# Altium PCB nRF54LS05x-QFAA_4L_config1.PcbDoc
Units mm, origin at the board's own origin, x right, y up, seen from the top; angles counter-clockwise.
Board outline 15 x 12 mm, 4 copper layers (Top Layer, Mid-Layer 1, Mid-Layer 2, Bottom Layer), stack 1.64 mm thick; 21 components, 51 nets, 91 pads, 73 vias.
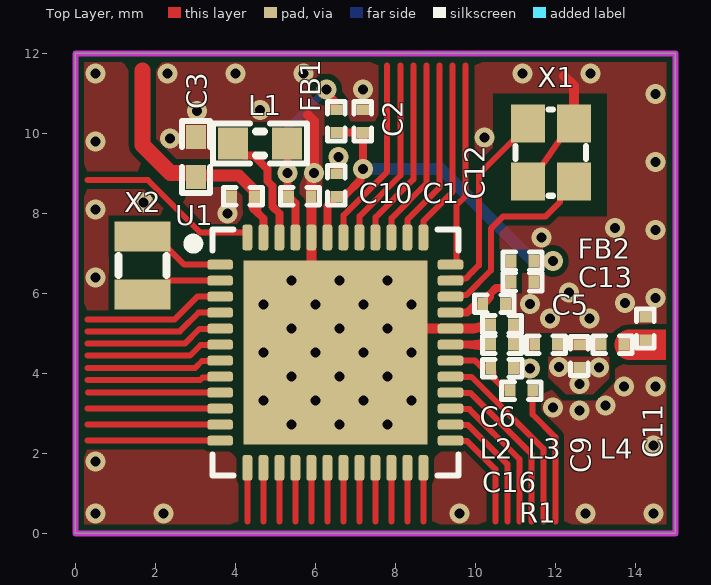
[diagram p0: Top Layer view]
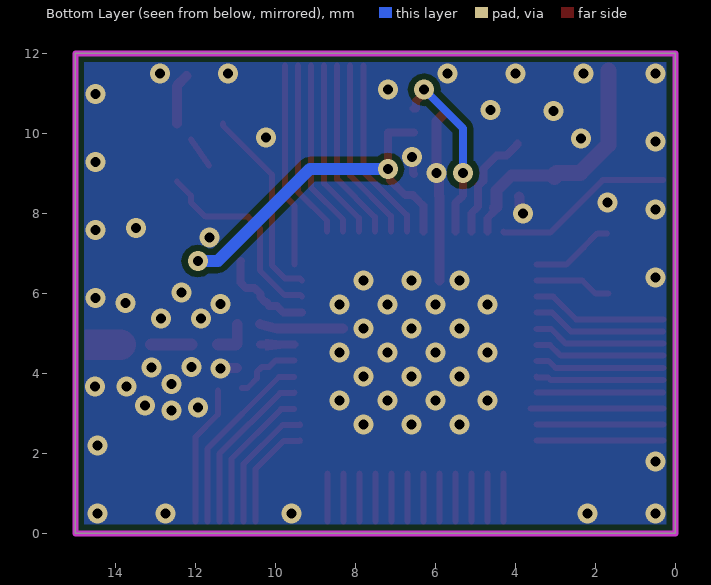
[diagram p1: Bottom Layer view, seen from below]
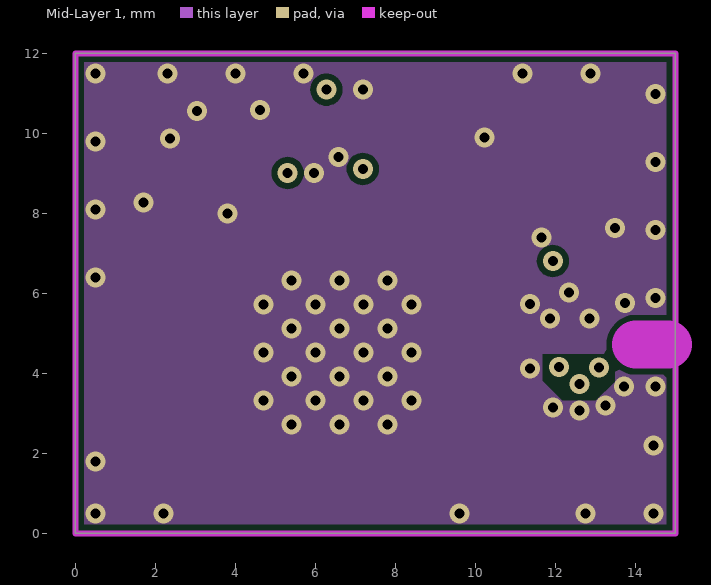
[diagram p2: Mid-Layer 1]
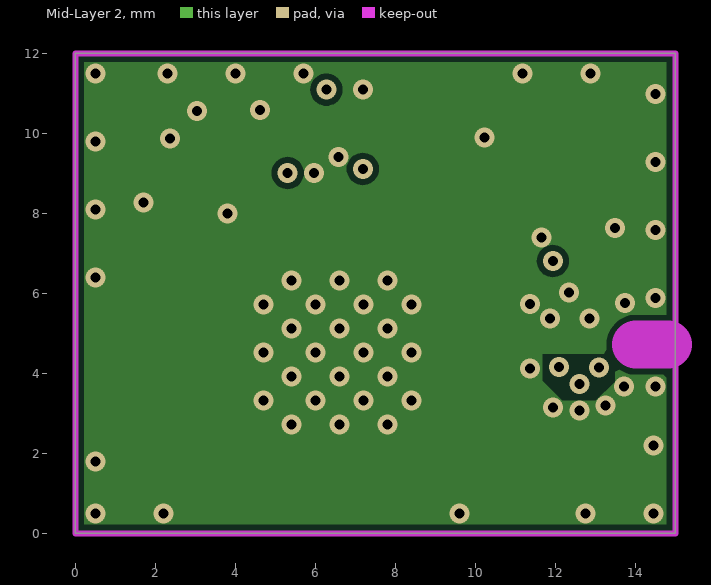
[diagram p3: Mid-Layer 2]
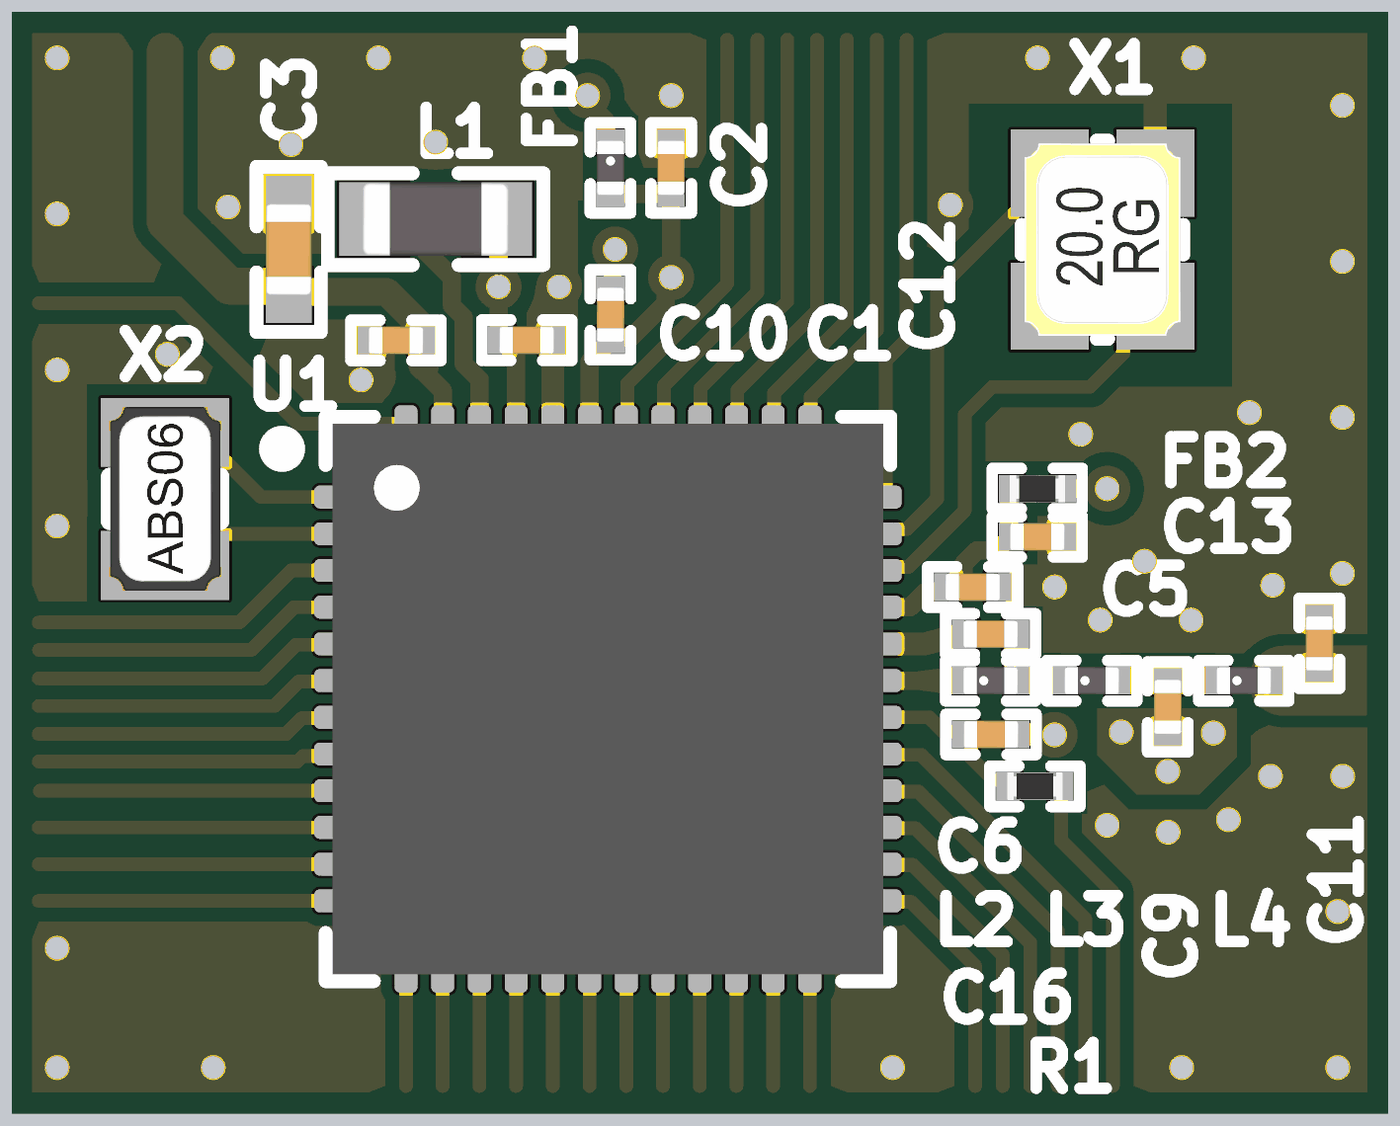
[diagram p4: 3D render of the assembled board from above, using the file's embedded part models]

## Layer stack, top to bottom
Top Solder: solder mask 0.0102, Solder Resist, Dk 3.5
Top Layer: signal copper 0.035
Dielectric 1: prepreg 0.1, 1080, Dk 4.3
Mid-Layer 1: signal copper 0.035
Dielectric 2: core 1.3, Core-042, Dk 4.6
Mid-Layer 2: signal copper 0.035
Dielectric 3: prepreg 0.1, 1080, Dk 4.3
Bottom Layer: signal copper 0.035
Bottom Solder: solder mask 0.0102, Solder Resist, Dk 3.5

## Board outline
0,0 0,12 15,12 15,0

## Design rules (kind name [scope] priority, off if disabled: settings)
Clearance Polygon_ANT [(InNamedPolygon('Top_Layer-GND')) or IsFill or IsRegion vs InNet('RF')] p1: gap=0.127 ignorepadtopadclearanceinfootprint=FALSE
Clearance Polygon [(InNamedPolygon('Top_Layer-GND'))  or (InNamedPolygon('Bottom_Layer-GND'))] p2: gap=0.15 ignorepadtopadclearanceinfootprint=FALSE
Clearance [All] p3: gap=0.15 ignorepadtopadclearanceinfootprint=FALSE
ComponentClearance [All] p1 off: gap=0.254 collisioncheckmode=3 verticalgap=0.254 showdistances=FALSE
FabricationTestPointUsage TestPointUsage [All] p1: valid=0 allowmultiple=FALSE
FabricationTestpoint Testpoint [All] p1: side=3 testpointundercomponent=TRUE minsize=1.016 maxsize=2.54 preferedsize=1.524 minholesize=0 maxholesize=1.016 preferedholesize=0.813 testpointgrid=0.025 allowsidetop=TRUE allowsidebottom=TRUE usegrid=TRUE gridtolerance=0
Height [All] p1 off: minheight=0 maxheight=25.4 prefheight=12.7
HoleSize [All] p1: absolutevalues=TRUE maxlimit=4.064 minlimit=0.2 maxpercent=80.000 minpercent=20.000
HoleToHoleClearance [All] p1: gap=0.36 allowstackedmicrovias=TRUE
MinimumAnnularRing [All] p1 off: minimumring=0.152
MinimumSolderMaskSliver [All] p1: minsoldermaskwidth=0.09
PlaneClearance [All] p1: clearance=0.2
PolygonConnect PolygonConnect_SMD_PADs [InComponent('C1','C2','C3','C4','C5','C7','C8','C9','C10','C11','C12','C13','C16') vs InNet('GND')] p1: connectstyle=Direct reliefconductorwidth=0.254 reliefentries=4 polygonreliefangle="90 Angle" airgapwidth=0.254
PolygonConnect PolygonConnect_GND_VIAs [isVia and innet(gnd)] p2: connectstyle=Direct reliefconductorwidth=0.254 reliefentries=4 polygonreliefangle="90 Angle" airgapwidth=0.254
PolygonConnect [All] p3: thpad.connectstyle=Relief thpad.reliefconductorwidth=0.25 thpad.reliefentries=4 thpad.polygonreliefangle="90 Angle" thpad.airgapwidth=0.2 smdpad.connectstyle=Relief smdpad.reliefconductorwidth=0.25 smdpad.reliefentries=4 smdpad.polygonreliefangle="90 Angle" smdpad.airgapwidth=0.2 via.connectstyle=Direct via.reliefconductorwidth=0.254 via.reliefentries=4 via.polygonreliefangle="90 Angle" via.airgapwidth=0.254
RoutingVias [All] p1: holewidth=0.406 width=0.813 viastyle="Through Hole" minholewidth=0.2 minwidth=0.4 maxholewidth=0.711 maxwidth=1.27
SilkToSolderMaskClearance SilkscreenOverComponentPads [IsPad] p1: minsilkscreentomaskgap=0.254 clearancetoexposedcopper=TRUE
SolderMaskExpansion SolderMaskExpansion_via [IsVia] p1: expansion=0.102 istentingtop=TRUE
SolderMaskExpansion [All] p2: expansion=0.03 istentingtop=FALSE
Width [All] p1: maxlimit=2.54 minlimit=0.15 preferedwidth=0.15
21 further rules are at their usual default settings.

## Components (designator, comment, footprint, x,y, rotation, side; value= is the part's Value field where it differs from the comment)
C1 "2.2µF" CAPC0603X03L_C 5.615,8.425 r180 top
C2 "2.2µF" CAPC0603X03L_C 7.188,10.303 r270 top
C3 "10µF" CAPC1005X04L 3.023,9.414 r270 top
C5 "10nF" CAPC0603X03L_C 10.473,5.735 r180 top
C6 "1.5pF" CAPC0603X03L_C 10.668,5.223 r0 top
C9 "2.0pF" CAPC0603X03L_C 12.598,4.43 r90 top
C10 "100nF" CAPC0603X03L_C 4.191,8.423 r0 top
C11 "0.3pF" CAPC0603X03L_C 14.249,5.121 r270 top
C12 "2.2µF" CAPC0603X03L_C 6.528,8.703 r90 top
C13 "2.2µF" CAPC0603X03L_C 11.177,6.283 r0 top
C16 "3.9pF" CAPC0603X03L_C 10.673,4.13 r0 top
FB1 "120R/0.2A" INDC0603X03L_C 6.528,10.303 r270 top
FB2 "0R" RESC0603X03L_C 11.177,6.807 r0 top
L1 "4.7µH" INDC1608X06L 4.623,9.744 r0 top
L2 "2.7nH" INDC0603X03L_C 10.668,4.715 r0 top
L3 "3.5nH" INDC0603X03L_C 11.77,4.715 r0 top
L4 "3.5nH" INDC0603X03L_C 13.426,4.715 r0 top
R1 "0R" RESC0603X03L_C 11.151,3.564 r0 top
U1 "nRF54LS05B-QFAA" QFN49P40_600x600x90L40x20T460N 6.5,4.516 r0 top locked
X1 "32MHz" BT-XTAL_2016 11.887,9.52 r90 top
X2 "32.768kHz" XTAL_2012 1.676,6.696 r90 top

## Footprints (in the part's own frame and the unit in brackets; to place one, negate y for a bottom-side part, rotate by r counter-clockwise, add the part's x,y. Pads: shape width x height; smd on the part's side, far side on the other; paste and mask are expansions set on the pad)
BT-XTAL_2016 [mm] "Crystal 2.0 x 1.6 mm"
  rect 0.95x0.85 smd: 1(-0.725,-0.575) 2(0.725,-0.575) 3(0.725,0.575) 4(-0.725,0.575)
  silkscreen extent -1.08,-0.88 1.08,0.88, body extent -1.05,-0.85 1.05,0.85, height 0.56
CAPC0603X03L_C [mm] "Chip Capacitor, 2-Leads, Body 0.6x0.3mm, IPC High Density"
  rect 0.27x0.3 smd mask+0.05: 1(-0.285,0) 2(0.285,0)
  silkscreen extent -0.49,-0.22 0.49,0.22, body extent -0.3,-0.15 0.3,0.15, height 0.3
CAPC1005X04L [mm] "Chip Capacitor, 2-Leads, Body 1.0x0.5mm, IPC High Density"
  rect 0.6x0.5 smd: 1(-0.5,0) 2(0.5,0)
  silkscreen extent -0.9,-0.35 0.9,0.35, body extent -0.5,-0.25 0.5,0.25, height 0.5
INDC0603X03L_C [mm] "Chip Inductor, 2-Leads, Body 0.6x0.3mm, IPC High Density"
  rect 0.27x0.3 smd: 1(-0.285,0) 2(0.285,0)
  silkscreen extent -0.49,-0.22 0.49,0.22, body extent -0.3,-0.15 0.3,0.15, height 0.3
INDC1608X06L [mm] "Chip Inductor, 2-Leads, Body 1.6x0.8mm, IPC High Density"
  rect 0.75x0.8 smd: 1(-0.675,0) 2(0.675,0)
  silkscreen extent -1.17,-0.5 1.17,0.5, body extent -0.8,-0.4 0.8,0.4, height 0.8
QFN49P40_600x600x90L40x20T460N [mm] "QFN, 48-Leads, Body 6.00x6.00mm, Pitch 0.40mm, Thermal Pad 4.60x4.60mm, IPC Nominal Density"
  rrect50% 0.64x0.25 smd mask+0.03: 1(-2.88,2.2) 2(-2.88,1.8) 3(-2.88,1.4) 4(-2.88,1) 5(-2.88,0.6) 6(-2.88,0.2) 7(-2.88,-0.2) 8(-2.88,-0.6) 9(-2.88,-1) 10(-2.88,-1.4) 11(-2.88,-1.8) 12(-2.88,-2.2) 25(2.88,-2.2) 26(2.88,-1.8) 27(2.88,-1.4) 28(2.88,-1) 29(2.88,-0.6) 30(2.88,-0.2) 31(2.88,0.2) 32(2.88,0.6) 33(2.88,1) 34(2.88,1.4) 35(2.88,1.8) 36(2.88,2.2)
  rrect50% 0.25x0.64 smd mask+0.03: 13(-2.2,-2.88) 14(-1.8,-2.88) 15(-1.4,-2.88) 16(-1,-2.88) 17(-0.6,-2.88) 18(-0.2,-2.88) 19(0.2,-2.88) 20(0.6,-2.88) 21(1,-2.88) 22(1.4,-2.88) 23(1.8,-2.88) 24(2.2,-2.88) 37(2.2,2.88) 38(1.8,2.88) 39(1.4,2.88) 40(1,2.88) 41(0.6,2.88) 42(0.2,2.88) 43(-0.2,2.88) 44(-0.6,2.88) 45(-1,2.88) 46(-1.4,2.88) 47(-1.8,2.88) 48(-2.2,2.88)
  rect 4.6x4.6 smd mask+0.05: 49(0,0)
  silkscreen extent -3.67,-3.08 3.08,3.08, body extent -3,-3 3,3, height 0.9
RESC0603X03L_C [mm] "Chip Resistor, 2-Leads, Body 0.6x0.3mm, IPC High Density"
  rect 0.27x0.3 smd: 1(-0.285,0) 2(0.285,0)
  silkscreen extent -0.49,-0.22 0.49,0.22, body extent -0.3,-0.15 0.3,0.15, height 0.23
XTAL_2012 [mm] "XTAL SMD 2.0 x 1.2 mm"
  rect 0.75x1.4 smd: 1(-0.725,0) 2(0.725,0)
  silkscreen extent -0.24,-0.6 0.24,0.6, body extent -1,-0.61 1,0.61, height 0.6

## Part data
C1 C2 C12 C13: library part C0201-2µ2-2.5V-X6T-GRM033D80E225ME47D, "Capacitor, Ceramic, 2.2µF 2.5V X6T 0201,±20%", Manufacturer=Murata, Manufacturer Part Number=GRM033D80E225ME47D, Part number IPS=N.A., Part number NEMS=100200527, Supplier Part Number 1=81-GRM033D80E225ME7D
C3: library part C0402-10µF-6.3V-X6S, "Capacitor, X6S, ±20%, 6.3V", Manufacturer=N.A., Part number NEMS=100200478
C5: library part C0201-10n-6.3V-X7R, "Capacitor, X7R, 6.3V", Manufacturer=Murata, Manufacturer Part Number=GRM033R70J103KA01D, Part number IPS=N.A., Part number NEMS=100200407, Supplier Part Number 1=490-1262-1-ND
C6: library part C0201-1.5p-25V-NP0-GJM0335C1E1R5WB01, "Capacitor, NP0, ±0.05pF, 25V, High Q", Manufacturer=Murata, Manufacturer Part Number=GJM0335C1E1R5WB01, Part number IPS=N.A., Part number NEMS=100200477, Supplier Part Number 1=490-11176-2-ND
C9: library part C0201-2.0p-HQ-Murata, "Capacitor, NP0, ±0.05pF, 25V", Manufacturer=Murata, Manufacturer Part Number=GJM0335C1E2R0WB01, Part number IPS=00000001775, Part number NEMS=100200419, Part number Norautron=N.A.
C10: library part C0201-100n-10V-X7R, "Capacitor, X7R, ±10%, 10V", Manufacturer=N.A., Part number NEMS=100200469
C11: library part C0201-0.3p-50V-GRM0335C1HR30BA01, "Capacitor, C0G, ±0.1pF, 50V", Manufacturer=Murata, Manufacturer Part Number=GRM0335C1HR30BA01, Part number IPS=N.A., Part number NEMS=100200650, Supplier Part Number 1=490-6135-2-ND
C16: library part C0201-3.9p, "Chip Cap 0201", Manufacturer=N.A., Part number NEMS=100200024,100200424
FB1: library part FB0201-120R@100M-200mA-BLM03AG121SN1D, "Ferrite Bead, 120 Ohm @ 100MHz, 200mA, 500 mOhm Max", Manufacturer=Murata, Manufacturer Part Number=BLM03AG121SN1D, Part number IPS=N.A., Part number NEMS=100300419, Supplier Part Number 1=490-5622-1-ND
FB2 R1: library part R0201-0R-5%-0.05W-RC0201JR-070RL, "0 Ohms Jumper 0.05W, 1/20W Chip Resistor 0201 (0603 Metric) Moisture Resistant Thick Film", Manufacturer=Yageo, Manufacturer Part Number=RC0201JR-070RL, Part number IPS=N.A., Part number NEMS=100100652, Supplier Part Number 1=311-0.0NCT-ND
L1: library part L0603-4µ7-MLZ1608M4R7WT000, "Inductor, 120mA, ±20%, 0.65R", Manufacturer="TDK Corporation", Manufacturer Part Number=MLZ1608M4R7WT000, Part number IPS=N.A., Part number NEMS=100300440, Supplier Part Number 1=445-6390-2-ND
L2: library part L0201-2n7-HQ-Murata, "Inductor, 600mA, ±0.1ｎH, 120mOhm", Manufacturer=Murata, Manufacturer Part Number=LQP03HQ2N7B02, Part number IPS=00000001753, Part number NEMS=100300214, Part number Norautron=N.A., Supplier Part Number 1=490-13909-1-ND
L3 L4: library part L0201-3n5-HQ-Murata, "Inductor, 500mA, ±0.1ｎH, 170mOhm", Manufacturer=Murata, Manufacturer Part Number=LQP03HQ3N5B02, Part number IPS=N.A., Part number NEMS=100300222, Supplier Part Number 1=490-13925-1-ND
U1: "Ultra-low-power Bluetooth LE SoC with 508 KB NVM and 96 KB  RAM, supporting Bluetooth LE and 2.4 GHz proprietary protocols", Manufacturer="Nordic Semiconductor", Part number IPS=N.A., Part number NEMS=102000422
X1: library part XTAL_SMD2016_32MHz_8pF_Kyocera, "XTAL SMD 2016, 32MHz, Cl=8pF, Tot: ±40ppm", Manufacturer=Kyocera, Manufacturer Part Number=CX2016DB32000D0WZRC1, Part number IPS=00000007827, Part number NEMS=101600039, Part number Norautron=26511136, Supplier Part Number 1=1253-1586-1-ND
X2: library part XTAL_SMD2012_32.768kHz_9pF_TXC, "XTAL SMD 2012, 32.768kHz, 9pF, ±20ppm", Manufacturer="TXC Corporation", Manufacturer Part Number=9HT11-32.768KDZC-T, Part number IPS=N.A., Part number NEMS=101600107, Supplier Part Number 1=887-1426-2-ND

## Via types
v1: diameter 0.5, hole 0.25, Top Layer to Bottom Layer, tented both sides, 73 vias

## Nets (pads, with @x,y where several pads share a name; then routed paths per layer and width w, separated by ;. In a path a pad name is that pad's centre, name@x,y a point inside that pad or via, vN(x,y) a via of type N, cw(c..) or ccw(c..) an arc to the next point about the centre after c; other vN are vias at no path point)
ANT: L2.1 U1.31 | length 0.9
  Top Layer w0.2: U1.31@9.525,4.716 10.382,4.716 L2.1
DCC: L1.1 U1.46 | length 2.8
  Top Layer w0.2: L1.1 3.948,9.719 4.223,9.444 4.466,9.444 4.801,9.109 4.801,8.804 4.928,8.677 4.928,8.172 5.1,8 U1.46@5.1,7.541
DECA: C2.2 C12.1 FB1.2 FB2.2 U1.43 | length 9.8
  Top Layer w0.2: U1.43@6.3,7.541 6.3,8.19 C12.1 6.563,8.453 6.75,8.453 7.131,8.833 7.131,9.052 v1(7.188,9.109) C2.2 ; FB1.2 C2.2@7.188,10.018 ; FB2.2 v1(11.939,6.807)
  Bottom Layer w0.3: v1@7.188,9.11 9.136,9.11 11.439,6.807 v1(11.939,6.807)
DECD: C1.2 FB1.1 L1.2 U1.45 | length 5.4
  Top Layer w0.2: L1.2@5.309,9.784 5.309,8.446 C1.2 5.33,8.41 5.365,8.375 5.38,8.375 5.5,8.255 5.5,7.766 U1.45@5.5,7.541 ; v1(6.278,11.09) 6.278,11.009 6.478,10.809 6.478,10.623 FB1.1@6.544,10.623
  Bottom Layer w0.2: v1(5.309,9.008) 5.309,10.125 6.274,11.09 v1(6.278,11.09)
DERF: C5.2 C13.1 FB2.1 U1.33 | length 2.5
  Top Layer w0.2: U1.33@9.33,5.516 9.793,5.516 9.962,5.685 10.153,5.685 C5.2@10.188,5.72 ; C5.2 10.188,5.75 10.223,5.785 10.256,5.785 10.373,5.902 10.373,5.989 10.519,6.135 10.738,6.135 10.871,6.268 C13.1@10.871,6.283 ; FB2.1@10.86,6.807 10.871,6.796 C13.1@10.871,6.272
GND: C1.1 C2.1 C3.1 C5.1 C6.1 C9.1 C10.1 C11.1 C12.2 C13.2 C16.2 U1.32 U1.44 U1.49 X1.2 X1.4 | length 9.7
  Top Layer w0.15: X1.4@11.662,9.195 X1.2@12.112,9.845
  Top Layer w0.2: C12.2 6.553,9.013 6.553,9.389 v1(6.579,9.414)
  Top Layer w0.25: v1(3.81,7.992) 3.81,8.059 3.896,8.145 3.896,8.413 C10.1 ; 5.817,10.455 5.969,10.303 5.969,8.94 5.91,8.881 5.91,8.435 C1.1 U1.49@5.9,6.316 ; U1.49@8.303,5.116 9.954,5.116 C6.1@10.381,5.23 ; C16.2 v1@11.361,4.13 ; 12.217,11.432 12.462,11.188 X1.2
  other v1: 0.5,0.5 2.2,0.5 9.6,0.5 12.75,0.5 14.45,0.5 0.5,1.8 14.45,2.2 5.4,2.716 6.6,2.716 7.8,2.716 12.601,3.064 11.938,3.14 13.259,3.2 4.7,3.316 6,3.316 7.2,3.316 8.4,3.316 13.716,3.674 14.503,3.674 12.598,3.727 5.4,3.916 6.6,3.916 7.8,3.916 11.366,4.125 13.094,4.145 12.091,4.156 4.7,4.516 6,4.516 7.2,4.516 8.4,4.516 5.4,5.116 6.6,5.116 7.8,5.116 11.862,5.375 12.852,5.375 4.7,5.716 6,5.716 7.2,5.716 8.4,5.716 11.366,5.736 13.741,5.756 14.5,5.883 12.345,6.016 5.4,6.316 6.6,6.316 7.8,6.316 0.5,6.4 11.65,7.4 14.5,7.583 13.487,7.636 0.5,8.1 1.7,8.271 5.969,9.008 14.5,9.283 0.5,9.8 2.362,9.877 10.23,9.9 3.048,10.557 4.623,10.582 14.5,10.983 7.188,11.09 0.5,11.5 2.3,11.5 4,11.5 5.7,11.5 11.18,11.5 12.88,11.5
NetC6_2: C6.2 L2.2 L3.1 | length 0.9
  Top Layer w0.27: L2.2@10.953,4.73 C6.2
  Top Layer w0.3: L2.2@10.98,4.715 L3.1@11.43,4.715
NetC9_2: C9.2 L3.2 L4.1 | length 1
  Top Layer w0.3: L3.2@12.091,4.715 C9.2 L4.1@13.106,4.715
NetC16_1: C16.1 R1.1 U1.30 | length 1.7
  Top Layer w0.15: U1.30@9.525,4.316 9.997,4.316 10.152,4.161 10.335,4.161 C16.1@10.385,4.111 ; C16.1@10.384,4.103 10.4,4.103 10.456,4.047 10.456,3.976 10.457,3.974 10.457,3.873 10.696,3.634 R1.1@10.836,3.634
NRESET: R1.2 | length 3.5
  Top Layer w0.15: R1.2 11.436,2.971 12,2.406 12,0.3
P0.00: U1.23 | length 1.2
  Top Layer w0.15: 8.3,0.3 U1.23@8.3,1.491
P0.01: U1.24 | length 1.2
  Top Layer w0.15: 8.7,0.3 U1.24@8.7,1.491
P0.02: U1.27 | length 3.6
  Top Layer w0.15: U1.27@9.535,3.106 9.853,3.106 11.1,1.859 11.1,0.3
P0.03: U1.28 | length 4.2
  Top Layer w0.15: U1.28@9.525,3.516 9.535,3.506 9.881,3.506 11.4,1.987 11.4,0.3
P0.04: U1.29 | length 4.7
  Top Layer w0.15: U1.29@9.534,3.907 9.909,3.907 11.7,2.116 11.7,0.3
P1.00/XL1: U1.1 X2.2 | length 2.1
  Top Layer w0.15: X2.2@1.702,7.497 1.951,7.497 2.301,7.147 2.301,7.138 2.723,6.716 U1.1@3.475,6.716
P1.01/XL2: U1.2 X2.1 | length 1.9
  Top Layer w0.15: X2.1@1.676,5.997 2.001,5.997 2.321,6.316 U1.2@3.475,6.316
P1.02: U1.3 | length 3.4
  Top Layer w0.15: 0.3,5.349 2.482,5.349 3.049,5.916 U1.3@3.475,5.916
P1.03: U1.4 | length 3.4
  Top Layer w0.15: 0.305,5.049 2.614,5.049 3.08,5.516 U1.4@3.475,5.516
P1.04/AIN0: U1.5 | length 3.3
  Top Layer w0.15: 0.3,4.74 2.736,4.74 3.103,5.107 U1.5@3.466,5.107
P1.05/AIN1: U1.6 | length 3.3
  Top Layer w0.15: 0.3,4.44 2.868,4.44 3.135,4.707 U1.6@3.466,4.707
P1.06/AIN2: U1.7 | length 3.2
  Top Layer w0.15: 0.3,4.135 2.995,4.135 3.167,4.307 U1.7@3.466,4.307
P1.07/AIN3: U1.8 | length 3.2
  Top Layer w0.15: 0.3,3.835 3.119,3.835 3.178,3.894 3.453,3.894 U1.8@3.475,3.916
P1.08: U1.9 | length 3.2
  Top Layer w0.15: 0.313,3.516 U1.9@3.475,3.516
P1.09: U1.37 | length 4.4
  Top Layer w0.15: U1.37@8.709,7.55 8.709,7.811 9.428,8.529 9.428,11.698
P1.10: U1.38 | length 4.5
  Top Layer w0.15: U1.38@8.309,7.55 8.309,7.85 9.103,8.643 9.103,11.698
P1.11: U1.39 | length 4.5
  Top Layer w0.15: U1.39@7.909,7.55 7.909,7.877 8.778,8.746 8.778,11.698
P1.12: U1.40 | length 4.5
  Top Layer w0.15: U1.40@7.51,7.551 7.51,7.904 8.453,8.847 8.453,11.699
P1.13: U1.41 | length 4.6
  Top Layer w0.15: U1.41@7.11,7.551 7.11,7.928 8.128,8.946 8.128,11.699
P1.14: U1.42 | length 4.6
  Top Layer w0.15: U1.42@6.71,7.551 6.71,7.952 7.798,9.041 7.798,11.699
P1.15: U1.48 | length 4.6
  Top Layer w0.15: 0.302,8.83 1.816,8.83 3.13,7.516 4.278,7.516 4.3,7.538 U1.48@4.3,7.541
P1.16: U1.10 | length 3.3
  Top Layer w0.15: 0.3,3.116 U1.10
P1.17: U1.11 | length 3.2
  Top Layer w0.15: 0.3,2.716 U1.11@3.475,2.716
P1.18: U1.12 | length 3.2
  Top Layer w0.15: 0.3,2.316 U1.12@3.475,2.316
P1.19: U1.13 | length 1.2
  Top Layer w0.15: 4.3,0.3 U1.13@4.3,1.491
P1.20: U1.14 | length 1.2
  Top Layer w0.15: 4.7,0.3 U1.14@4.7,1.491
P1.21: U1.15 | length 1.2
  Top Layer w0.15: 5.1,0.3 U1.15@5.1,1.491
P1.22: U1.16 | length 1.2
  Top Layer w0.15: 5.5,0.3 U1.16@5.5,1.491
P1.23: U1.17 | length 1.2
  Top Layer w0.15: 5.9,0.3 U1.17@5.9,1.491
P1.24: U1.18 | length 1.2
  Top Layer w0.15: 6.3,0.3 U1.18@6.3,1.491
P1.25: U1.19 | length 1.2
  Top Layer w0.15: 6.7,0.3 U1.19@6.7,1.491
P1.26: U1.20 | length 1.2
  Top Layer w0.15: 7.1,0.3 U1.20@7.1,1.491
P1.27: U1.21 | length 1.2
  Top Layer w0.15: 7.5,0.3 U1.21@7.5,1.491
P1.28: U1.22 | length 1.2
  Top Layer w0.15: 7.9,0.3 U1.22@7.9,1.491
P1.29/SWDIO: U1.25 | length 2.7
  Top Layer w0.15: U1.25 9.39,2.306 9.798,2.306 10.5,1.604 10.5,0.3
P1.30/SWDCLK: U1.26 | length 3.3
  Top Layer w0.15: 9.822,2.706 10.8,1.728 10.8,0.3
  Top Layer w0.152: U1.26 9.39,2.706 9.822,2.706
P1.31: U1.36 | length 5.1
  Top Layer w0.15: U1.36@9.525,6.716 9.525,8.199 9.754,8.428 9.754,11.698
RF: C11.2 L4.2 | length 0.5
  Top Layer w0.762: 13.86,4.715 C11.2@14.367,4.715
VDD_NRF: C3.2 C10.2 U1.47 | length 6.3
  Top Layer w0.2: 4.504,8.127 4.504,8.071 4.7,7.875 U1.47@4.7,7.541
  Top Layer w0.3: C3.2@3.023,8.951 4.09,8.951 4.476,8.566 C10.2 4.476,8.156 4.504,8.127
  Top Layer w0.4: 1.676,11.574 1.676,9.714 2.376,9.014 2.973,9.014 3.023,8.964 C3.2
XC1: U1.34 X1.1 | length 5
  Top Layer w0.15: U1.34@9.33,5.916 9.367,5.953 9.77,5.953 10.386,6.569 10.386,7.616 10.686,7.916 11.751,7.916 12.112,8.277 12.112,8.445 X1.1
XC2: U1.35 X1.3 | length 5
  Top Layer w0.15: U1.35@9.33,6.316 9.38,6.366 9.757,6.366 9.925,6.534 9.925,6.538 10.086,6.699 10.086,8.969 11.312,10.195 X1.3

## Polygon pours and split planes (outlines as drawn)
GND on Top Layer "Top_Layer-GND" (solid, remove dead copper, pour order 1004): 0,12 0,0 15,0 15,12
GND on Top Layer "GND_island" (solid, pour order 1000): 11.776,4.414 11.776,3.905 12.207,3.473 12.893,3.473 13.299,3.878 13.299,4.413
GND on Bottom Layer "Bottom_Layer-GND" (solid, remove dead copper, pour order 1001): 0,12 0,0 15,0 15,12
GND on Mid-Layer 1 "Top_Layer-GND" (solid, remove dead copper, pour order 1002): 0,12 0,0 15,0 15,12
GND on Mid-Layer 2 "Top_Layer-GND" (solid, remove dead copper, pour order 1003): 0,12 0,0 15,0 15,12

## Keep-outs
Mid-Layer 1:
  lines w1.2: 14.019,4.715 14.812,4.715
Mid-Layer 2:
  lines w1.2: 14.019,4.715 14.812,4.715
Keep-Out Layer:
  the board outline again, w0.15

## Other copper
Top Layer:
  rectangle net RF: 14.3,4.334 14.765,5.096
  pour cut-out: 11.826,4.413 11.826,3.905 12.258,3.473 12.944,3.473 13.35,3.879 13.35,3.88 13.35,4.413 13.5,4.413 13.5,3.793 13.018,3.31 12.179,3.31 11.671,3.818 11.671,4.413
  pour cut-out: 10.705,5.786 10.705,5.577 10.818,5.577 10.818,5.786
  region net ANT: 10.248,4.865 9.859,4.815 9.859,4.616 10.248,4.565
  pour cut-out: 6.985,8.601 6.172,8.601 6.172,9.947 6.985,9.947
  pour cut-out: 0.833,6.904 0.833,6.493 0.945,6.493 0.945,6.904
  pour cut-out: 4.753,10.278 4.543,10.278 4.543,10.165 4.753,10.165
  pour cut-out: 13.3,11 13.3,7.916 10.432,7.916 10.432,11
Mid-Layer 1:
  pour cut-out: 11.67,4.493 11.67,3.818 12.178,3.31 13.017,3.31 13.499,3.793 13.499,4.493
Mid-Layer 2:
  pour cut-out: 11.67,4.493 11.67,3.818 12.178,3.31 13.017,3.31 13.499,3.793 13.499,4.493

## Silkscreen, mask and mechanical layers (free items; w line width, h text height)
Mechanical 1:
  the board outline again, w0.15

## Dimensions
15,12 to 15,0 on Mechanical 3
0,0 to 15,0 on Mechanical 3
